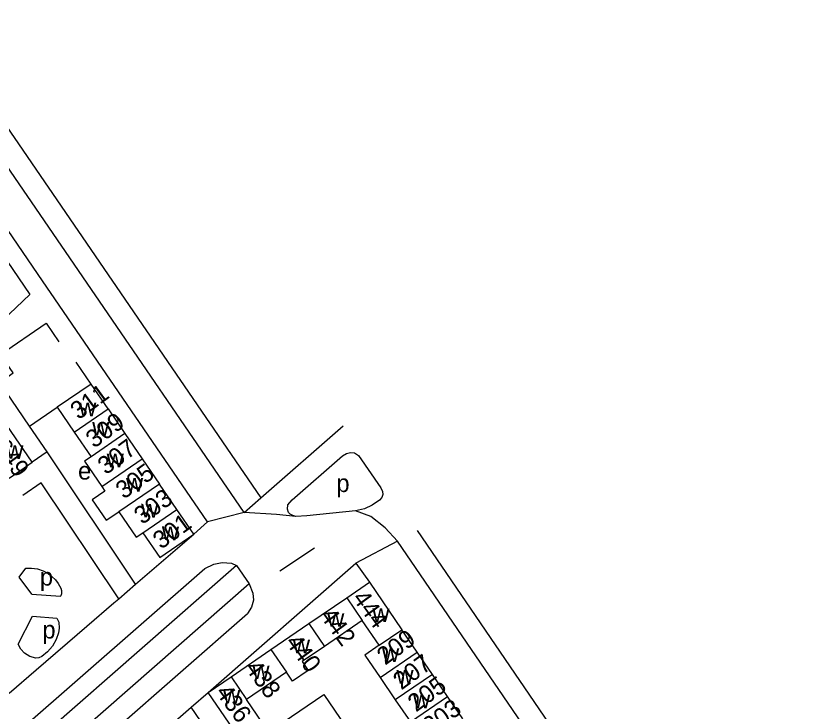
# Model space of a CAD drawing. Extents: x 154320 to 156262, y 382651 to 384180.
# Drawn here: x 156007.7 to 156189.4, y 383306.8 to 383463.8 of the extents above; entities that cross this region are included whole.
import ezdxf

# ---------------------------------------------------------------- set-up
doc = ezdxf.new("R2010")
doc.units = 0
for name, color, linetype in [('BLT_Basislijn', 7, 'Continuous'), ('BLT_Bebouwing', 7, 'Continuous'), ('BLT_Centroide', 7, 'Continuous'), ('BLT_Huisnummer', 7, 'Continuous'), ('BLT_Huisnummer_ tussenligend', 7, 'Continuous'), ('BLT_Onderverdeling_panden', 7, 'Continuous'), ('BLT_Vlakafsluiter', 7, 'Continuous')]:
    doc.layers.add(name, color=color, linetype=linetype)

msp = doc.modelspace()

# ---------------------------------------------------------------- linework, layer by layer
at = {"layer": 'BLT_Basislijn'}
for p, q in [((155988.48, 383463.76), (156062.92, 383355.09)), ((156024.62, 383380.7), (156021.23, 383385.66)), ((156062.92, 383355.09), (156081.43, 383371.3)), ((156059.13, 383351.78), (156062.92, 383355.09)), ((156047.74, 383346.87), (156050.88, 383349.67)), ((156034.65, 383335.58), (156047.74, 383346.87)), ((156067.17, 383338.63), (156074.96, 383343.8)), ((156050.98, 383311.16), (156084.28, 383340.34)), ((156084.28, 383340.34), (156087.38, 383336.03)), ((156057.41, 383339.79), (155935.41, 383232.93)), ((155937.39, 383240.46), (156050.24, 383339.15)), ((156057.41, 383339.79), (156060.26, 383335.64)), ((156011.26, 383333.37), (156008.41, 383337.18)), ((156060.26, 383335.64), (155938.63, 383229.11)), ((156030.84, 383332.28), (156034.65, 383335.58)), ((156023.66, 383326.09), (156029.75, 383331.35)), ((156029.75, 383331.35), (156030.84, 383332.28)), ((155946.6, 383229.91), (156059.86, 383328.96)), ((156012.26, 383316.25), (156023.66, 383326.09)), ((156006.17, 383311), (156012.26, 383316.25)), ((156047.19, 383307.85), (156050.98, 383311.16)), ((156036.31, 383298.35), (156047.19, 383307.85))]:
    msp.add_line(p, q, dxfattribs=at)
for points in [[(156059.13, 383351.78), (155984.36, 383460.93)], [(155992.7, 383427.46), (156010.8, 383400.93), (155937.34, 383331.15)], [(156012.64, 383405.48), (156001.19, 383422.21)], [(156050.88, 383349.67), (156012.64, 383405.48)], [(156010.72, 383371.23), (156003.96, 383381.13), (156007.05, 383383.25), (156004.17, 383387.44), (156014.47, 383394.49), (156017.34, 383390.3)], [(156014.73, 383365.44), (156010.72, 383371.23), (156016.99, 383375.5)], [(156014.73, 383365.44), (156011.3, 383363.09)], [(156034.65, 383335.58), (156014.73, 383365.44)], [(156070.77, 383350.89), (156070.07, 383351.11), (156069.47, 383351.42), (156069.12, 383351.8), (156068.92, 383352.49), (156068.97, 383353.47), (156069.94, 383354.59), (156081.31, 383364.54)], [(156081.31, 383364.54), (156082.22, 383365.1), (156083.07, 383365.3), (156084.01, 383365.25), (156084.94, 383364.65), (156089.98, 383357.35), (156090.33, 383356.51), (156090.4, 383355.81), (156090.2, 383355.15), (156089.64, 383354.53)], [(156030.84, 383332.28), (156013.38, 383358.45), (156009.25, 383355.63)], [(156089.64, 383354.53), (156088.02, 383353.42), (156086.26, 383352.61), (156084.27, 383352.12)], [(156070.77, 383350.89), (156066.45, 383351.28), (156059.13, 383351.78)], [(156084.27, 383352.12), (156073.25, 383351.03), (156070.77, 383350.89)], [(156093.74, 383345.32), (156090.92, 383348.34), (156087.7, 383350.85), (156084.27, 383352.12)], [(156189.4, 383214.02), (156098.19, 383347.67)], [(156185.27, 383211.2), (156093.74, 383345.32)], [(156050.24, 383339.15), (156052.25, 383340.11), (156054.14, 383340.47), (156056.26, 383340.34), (156057.41, 383339.79)], [(156008.41, 383337.18), (156009.92, 383339.24)], [(156009.92, 383339.24), (156011.17, 383339.24), (156012.5, 383339.02), (156013.78, 383338.58), (156014.9, 383337.99), (156015.76, 383337.36), (156016.59, 383336.55), (156017.21, 383335.72), (156017.77, 383334.69), (156017.94, 383334.14), (156017.92, 383333.41), (156017.78, 383332.95), (156017.74, 383332.89)], [(156060.26, 383335.64), (156061.1, 383333.55), (156061.25, 383331.95), (156060.8, 383330.41), (156059.86, 383328.96)], [(156011.26, 383333.37), (156017.74, 383332.89)], [(156008.18, 383322.06), (156011.4, 383328.35), (156016.9, 383327.94)], [(156016.9, 383327.94), (156017.3, 383327), (156017.44, 383325.65), (156017.24, 383324.61), (156016.74, 383323.11), (156015.89, 383321.59), (156014.79, 383320.31), (156013.51, 383319.29), (156012.84, 383318.97), (156012.14, 383318.92), (156010.78, 383319.27), (156009.59, 383319.99), (156008.75, 383320.9), (156008.18, 383322.06)], [(156067.93, 383304.46), (156077.07, 383310.67), (156091.4, 383289.75)], [(156062.9, 383275.95), (156067.08, 383278.7), (156047.19, 383307.85)]]:
    msp.add_lwpolyline(points, dxfattribs=at)
at = {"layer": 'BLT_Bebouwing'}
for p, q in [((156024.62, 383380.7), (156016.99, 383375.5)), ((156028.43, 383375.12), (156024.62, 383380.7)), ((156028.43, 383375.12), (156032.24, 383369.55)), ((156011.3, 383363.09), (156005.58, 383371.49)), ((156020.8, 383369.92), (156024.6, 383364.34)), ((156032.24, 383369.55), (156036.14, 383363.84)), ((156036.14, 383363.84), (156040.03, 383358.14)), ((156008.75, 383361.35), (156011.3, 383363.09)), ((156006.1, 383359.54), (156008.75, 383361.35)), ((156043.93, 383352.44), (156040.03, 383358.14)), ((156047.74, 383346.87), (156043.93, 383352.44)), ((156082.26, 383332.53), (156087.38, 383336.03)), ((156087.38, 383336.03), (156094.71, 383325.3)), ((156073.71, 383326.69), (156082.26, 383332.53)), ((156085.77, 383327.39), (156077.21, 383321.55)), ((156089.6, 383321.8), (156085.77, 383327.39)), ((156065.15, 383320.84), (156073.71, 383326.69)), ((156098.14, 383320.27), (156094.71, 383325.3)), ((156056.17, 383314.7), (156065.15, 383320.84)), ((156101.57, 383315.24), (156098.14, 383320.27)), ((156068.65, 383315.71), (156059.65, 383309.57)), ((156089.76, 383314.55), (156093.18, 383309.52)), ((156105.01, 383310.22), (156101.57, 383315.24)), ((156064.64, 383302.23), (156059.65, 383309.57)), ((156093.18, 383309.52), (156096.61, 383304.5)), ((156108.44, 383305.2), (156105.01, 383310.22))]:
    msp.add_line(p, q, dxfattribs=at)
for points in [[(156016.99, 383375.5), (156020.8, 383369.92)], [(156024.6, 383364.34), (156023.11, 383363.33), (156027.01, 383357.61)], [(156027.01, 383357.61), (156027.72, 383356.56), (156024.87, 383354.62), (156027.98, 383350.05), (156030.9, 383351.9)], [(156030.9, 383351.9), (156034.79, 383346.19), (156036.27, 383347.21)], [(156036.27, 383347.21), (156040.09, 383341.63), (156047.74, 383346.87)], [(156089.6, 383321.8), (156086.33, 383319.57), (156089.76, 383314.55)], [(156077.21, 383321.55), (156072.22, 383318.14), (156073.58, 383316.15), (156070.01, 383313.72), (156068.65, 383315.71)], [(156050.98, 383311.16), (156056.17, 383314.7)], [(156059.47, 383298.72), (156050.98, 383311.16)]]:
    msp.add_lwpolyline(points, dxfattribs=at)
at = {"layer": 'BLT_Onderverdeling_panden'}
for p, q in [((156020.8, 383369.92), (156028.43, 383375.12)), ((156032.24, 383369.55), (156024.6, 383364.34)), ((156027.01, 383357.61), (156036.14, 383363.84)), ((156040.03, 383358.14), (156030.9, 383351.9)), ((156036.27, 383347.21), (156043.93, 383352.44)), ((156082.26, 383332.53), (156085.77, 383327.39)), ((156073.71, 383326.69), (156077.21, 383321.55)), ((156089.6, 383321.8), (156094.71, 383325.3)), ((156065.15, 383320.84), (156068.65, 383315.71)), ((156089.76, 383314.55), (156098.14, 383320.27)), ((156056.17, 383314.7), (156059.65, 383309.57)), ((156101.57, 383315.24), (156093.18, 383309.52)), ((156096.61, 383304.5), (156105.01, 383310.22))]:
    msp.add_line(p, q, dxfattribs=at)
at = {"layer": 'BLT_Vlakafsluiter'}
for p, q in [((156059.13, 383351.78), (156050.88, 383349.67)), ((156093.74, 383345.32), (156084.28, 383340.34))]:
    msp.add_line(p, q, dxfattribs=at)

# ---------------------------------------------------------------- texts
at = {"layer": 'BLT_Centroide'}
for p in [(156021.89, 383373.49), (156024.84, 383369.12), (156005.47, 383363.89), (156028.1, 383361.98), (156032.46, 383356.5), (156035.88, 383350.65), (156040.55, 383345.54), (156077.83, 383326.01), (156088.02, 383327.06), (156070.08, 383320.02), (156090.21, 383318.08), (156060.97, 383314.2), (156093.44, 383313.17), (156054.36, 383308.7), (156097.2, 383307.63)]:
    msp.add_text('w', height=4, rotation=359.5, dxfattribs=at).set_placement(p)
for s, p in [('e', (156021.67, 383359.19)), ('p', (156079.92, 383356.38)), ('p', (156013.06, 383335.27)), ('p', (156013.63, 383323.33))]:
    msp.add_text(s, height=4, dxfattribs=at).set_placement(p)
at = {"layer": 'BLT_Huisnummer'}
for s, rotation, p in [('311', 36.0883, (156021.8, 383372.56)), ('309', 36.0883, (156025.28, 383366.13)), ('649', 306.0883, (156002.46, 383366.58)), ('305', 36.0883, (156032.01, 383354.64)), ('301', 36.0883, (156040.41, 383343.33)), ('444', 306.0883, (156083.38, 383332.42)), ('209', 36.0883, (156090.92, 383317.19)), ('440', 306.0883, (156068.28, 383322.5)), ('205', 36.0883, (156097.88, 383306.62)), ('436', 306.0883, (156052.55, 383311.17))]:
    msp.add_text(s, height=4, rotation=rotation, dxfattribs=at).set_placement(p)
at = {"layer": 'BLT_Huisnummer_ tussenligend'}
for s, rotation, p in [('307', 36.0883, (156027.95, 383360.14)), ('303', 36.0883, (156036.15, 383348.9)), ('442', 306.0883, (156076.04, 383328.47)), ('207', 36.0883, (156094.57, 383311.59)), ('438', 306.0883, (156059.17, 383316.67)), ('203', 36.0883, (156101.24, 383301.48))]:
    msp.add_text(s, height=4, rotation=rotation, dxfattribs=at).set_placement(p)

doc.saveas('drawing.dxf')
